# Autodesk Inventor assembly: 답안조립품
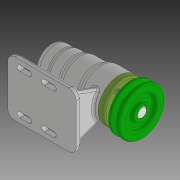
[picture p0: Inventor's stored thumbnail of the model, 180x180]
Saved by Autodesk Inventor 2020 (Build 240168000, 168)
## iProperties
Created: 2021-10
Part Number: 답안조립품
Document SubType Name: Assembly
Designer: user
Author: user
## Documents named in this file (12)
- C:\Users\user\Desktop\711007V1005\답안조립품.iam
- C:\Users\user\Desktop\711007V1005\V벨트풀리.ipt
- C:\Users\user\Desktop\711007V1005\멈춤나사 M3.ipt
- C:\Users\user\Desktop\711007V1005\베어링 6004.ipt
- C:\Users\user\Desktop\711007V1005\베어링 51202.ipt
- C:\Users\user\Desktop\711007V1005\본체.ipt
- C:\Users\user\Desktop\711007V1005\볼트 M4.ipt
- C:\Users\user\Desktop\711007V1005\어댑터슬리브.ipt
- C:\Users\user\Desktop\711007V1005\오일 실 20x35x7.ipt
- C:\Users\user\Desktop\711007V1005\축.ipt
- C:\Users\user\Desktop\711007V1005\커버.ipt
- C:\Users\user\Desktop\711007V1005\키 5x5.ipt
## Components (1 placed, 1 different names)
1. V벨트풀리:1 — 플러쉬:1
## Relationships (1: Flush 1)
- 플러쉬:1 [Flush]: V벨트풀리:1
